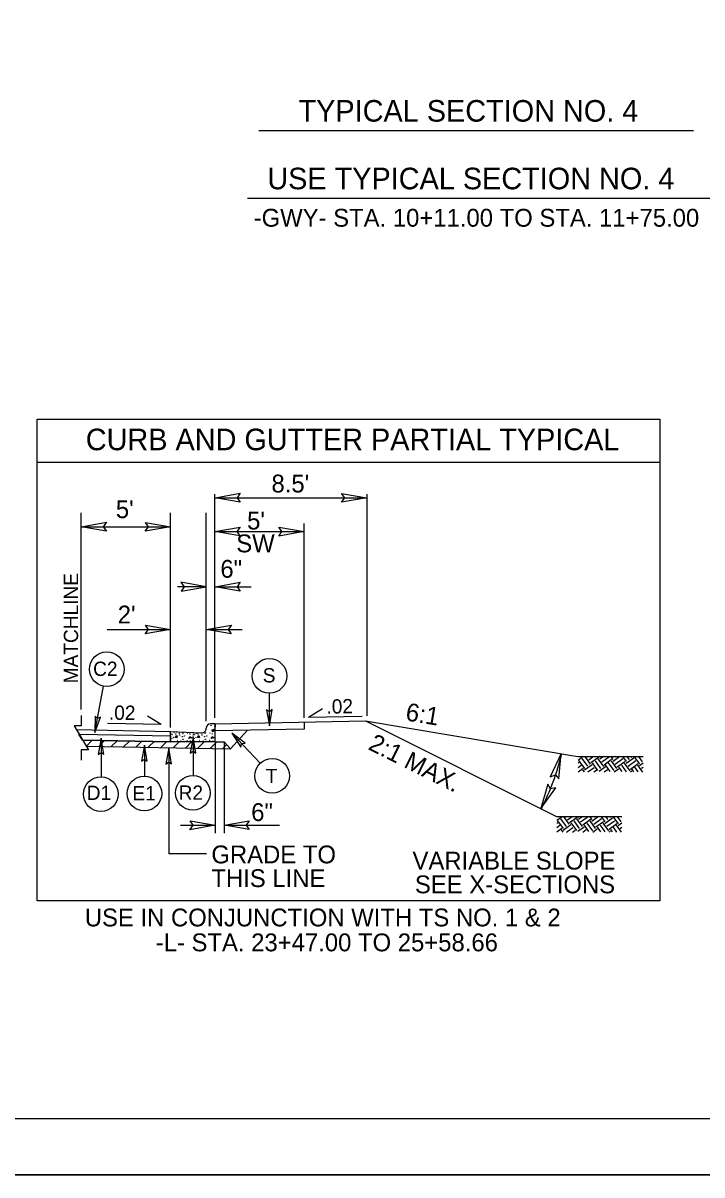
# Model space of a CAD drawing. Extents: x 1184121 to 1184397, y 1246506 to 1246661.
# Drawn here: x 1184280.8 to 1184318.8, y 1246505.7 to 1246570.3 of the extents above; entities that cross this region are included whole.
import ezdxf

# ---------------------------------------------------------------- set-up
doc = ezdxf.new("R2010")
doc.units = 0
for name, color, linetype in [('Prop Shade Light', 7, 'Continuous'), ('Sheet Data Field CELL', 7, 'Continuous'), ('Sheet Plan CELL', 7, 'Continuous'), ('Sheet Plot Border Outside CELL', 7, 'Continuous'), ('Typical Text Label CELL', 7, 'Continuous'), ('z - Construction', 7, 'Continuous')]:
    doc.layers.add(name, color=color, linetype=linetype)

msp = doc.modelspace()

# ---------------------------------------------------------------- linework, layer by layer
at = {"layer": 'Prop Shade Light'}
msp.add_lwpolyline([(1184289.029, 1246529.977), (1184284.1, 1246530.076), (1184283.897, 1246530.413), (1184289.024, 1246530.31), (1184289.029, 1246530.31)], close=True, dxfattribs=at)
at = {"layer": 'Sheet Data Field CELL'}
for p, q in [((1184293.971, 1246564.23), (1184318.347, 1246564.23)), ((1184293.343, 1246560.441), (1184319.777, 1246560.441)), ((1184291.513, 1246531.313), (1184291.513, 1246543.855)), ((1184300.046, 1246531.428), (1184300.046, 1246543.855)), ((1184291.529, 1246543.654), (1184300.046, 1246543.654)), ((1184284.029, 1246531.779), (1184284.029, 1246542.815)), ((1184289.029, 1246530.772), (1184289.029, 1246542.815)), ((1184291.029, 1246531.132), (1184291.029, 1246542.815)), ((1184284.029, 1246542.032), (1184289.029, 1246542.032)), ((1184296.513, 1246532.378), (1184296.513, 1246542.211)), ((1184291.513, 1246541.756), (1184296.513, 1246541.756)), ((1184291.029, 1246538.665), (1184289.425, 1246538.665)), ((1184291.529, 1246538.665), (1184293.551, 1246538.665)), ((1184285.477, 1246536.272), (1184289.029, 1246536.272)), ((1184291.029, 1246536.272), (1184293.051, 1246536.272)), ((1184284.785, 1246530.497), (1184285.281, 1246533.089)), ((1184294.572, 1246530.865), (1184294.571, 1246532.694)), ((1184296.513, 1246531.313), (1184296.513, 1246532.378)), ((1184296.757, 1246531.363), (1184297.54, 1246531.836)), ((1184288.515, 1246530.941), (1184285.499, 1246531.002)), ((1184288.515, 1246530.941), (1184287.732, 1246531.415)), ((1184291.529, 1246530.977), (1184291.268, 1246530.977)), ((1184291.529, 1246530.977), (1184291.523, 1246530.588)), ((1184291.529, 1246530.977), (1184299.967, 1246531.146)), ((1184291.529, 1246529.977), (1184291.529, 1246530.977)), ((1184296.528, 1246531.077), (1184296.522, 1246530.688)), ((1184296.757, 1246531.363), (1184299.774, 1246531.423)), ((1184299.967, 1246531.146), (1184311.858, 1246529.164)), ((1184299.967, 1246531.146), (1184310.665, 1246525.797)), ((1184283.745, 1246530.666), (1184289.029, 1246530.56)), ((1184283.897, 1246530.413), (1184289.024, 1246530.31)), ((1184285.14, 1246530.187), (1184285.14, 1246528.02)), ((1184289.029, 1246530.56), (1184289.029, 1246530.55)), ((1184289.029, 1246529.977), (1184289.029, 1246530.56)), ((1184289.029, 1246530.56), (1184290.779, 1246530.488)), ((1184289.289, 1246530.217), (1184289.376, 1246530.337)), ((1184289.41, 1246530.223), (1184289.289, 1246530.217)), ((1184289.376, 1246530.337), (1184289.41, 1246530.223)), ((1184290.055, 1246530.166), (1184290.117, 1246530.28)), ((1184290.221, 1246530.205), (1184290.055, 1246530.166)), ((1184290.117, 1246530.28), (1184290.221, 1246530.205)), ((1184290.295, 1246530.254), (1184290.295, 1246528.087)), ((1184290.539, 1246530.217), (1184290.625, 1246530.337)), ((1184290.659, 1246530.223), (1184290.539, 1246530.217)), ((1184290.625, 1246530.337), (1184290.659, 1246530.223)), ((1184291.029, 1246530.727), (1184291.029, 1246530.738)), ((1184291.304, 1246530.166), (1184291.366, 1246530.28)), ((1184291.469, 1246530.205), (1184291.304, 1246530.166)), ((1184291.338, 1246530.644), (1184291.355, 1246530.553)), ((1184291.492, 1246530.599), (1184291.338, 1246530.644)), ((1184291.355, 1246530.553), (1184291.492, 1246530.599)), ((1184291.366, 1246530.28), (1184291.469, 1246530.205)), ((1184296.522, 1246530.688), (1184291.523, 1246530.588)), ((1184293.349, 1246530.624), (1184292.394, 1246529.577)), ((1184292.465, 1246530.455), (1184294.061, 1246528.774)), ((1184284.1, 1246530.076), (1184289.029, 1246529.977)), ((1184284.302, 1246529.739), (1184292.394, 1246529.577)), ((1184284.318, 1246529.738), (1184284.645, 1246530.065)), ((1184285.012, 1246529.724), (1184285.338, 1246530.051)), ((1184285.705, 1246529.711), (1184286.031, 1246530.037)), ((1184286.398, 1246529.697), (1184286.725, 1246530.023)), ((1184287.091, 1246529.683), (1184287.418, 1246530.009)), ((1184287.565, 1246529.798), (1184287.565, 1246528.053)), ((1184287.785, 1246529.669), (1184288.111, 1246529.996)), ((1184288.478, 1246529.655), (1184288.805, 1246529.982)), ((1184288.933, 1246529.646), (1184288.933, 1246523.696)), ((1184291.529, 1246529.977), (1184289.029, 1246529.977)), ((1184289.171, 1246529.641), (1184289.507, 1246529.977)), ((1184289.864, 1246529.627), (1184290.214, 1246529.977)), ((1184290.558, 1246529.613), (1184290.922, 1246529.977)), ((1184291.251, 1246529.6), (1184291.629, 1246529.977)), ((1184291.529, 1246529.977), (1184292.029, 1246529.977)), ((1184291.529, 1246529.977), (1184291.529, 1246524.865)), ((1184291.944, 1246529.586), (1184292.175, 1246529.817)), ((1184292.029, 1246529.977), (1184292.394, 1246529.577)), ((1184292.029, 1246529.977), (1184292.029, 1246524.865)), ((1184311.858, 1246529.164), (1184315.513, 1246529.164)), ((1184311.858, 1246529.164), (1184315.513, 1246529.164)), ((1184311.872, 1246528.952), (1184312.168, 1246529.165)), ((1184311.872, 1246528.952), (1184312.168, 1246529.165)), ((1184312.251, 1246528.491), (1184311.942, 1246528.921)), ((1184312.251, 1246528.491), (1184311.942, 1246528.921)), ((1184312.412, 1246528.607), (1184312.103, 1246529.037)), ((1184312.412, 1246528.607), (1184312.103, 1246529.037)), ((1184312.573, 1246528.723), (1184312.264, 1246529.152)), ((1184312.573, 1246528.723), (1184312.264, 1246529.152)), ((1184312.357, 1246529.137), (1184312.395, 1246529.165)), ((1184312.357, 1246529.137), (1184312.395, 1246529.165)), ((1184312.473, 1246528.976), (1184312.737, 1246529.166)), ((1184312.473, 1246528.976), (1184312.737, 1246529.166)), ((1184312.588, 1246528.815), (1184313.018, 1246529.124)), ((1184312.588, 1246528.815), (1184313.018, 1246529.124)), ((1184313.15, 1246528.486), (1184312.842, 1246528.916)), ((1184313.15, 1246528.486), (1184312.842, 1246528.916)), ((1184313.312, 1246528.602), (1184313.003, 1246529.032)), ((1184313.312, 1246528.602), (1184313.003, 1246529.032)), ((1184313.11, 1246529.109), (1184313.068, 1246529.167)), ((1184313.11, 1246529.109), (1184313.068, 1246529.167)), ((1184313.095, 1246529.016), (1184313.306, 1246529.168)), ((1184313.095, 1246529.016), (1184313.306, 1246529.168)), ((1184313.211, 1246528.855), (1184313.641, 1246529.164)), ((1184313.211, 1246528.855), (1184313.641, 1246529.164)), ((1184313.327, 1246528.694), (1184313.756, 1246529.003)), ((1184313.327, 1246528.694), (1184313.756, 1246529.003)), ((1184313.849, 1246528.988), (1184313.719, 1246529.169)), ((1184313.849, 1246528.988), (1184313.719, 1246529.169)), ((1184314.05, 1246528.481), (1184313.741, 1246528.911)), ((1184314.05, 1246528.481), (1184313.741, 1246528.911)), ((1184313.834, 1246528.896), (1184314.216, 1246529.17)), ((1184313.834, 1246528.896), (1184314.216, 1246529.17)), ((1184313.949, 1246528.734), (1184314.379, 1246529.043)), ((1184313.949, 1246528.734), (1184314.379, 1246529.043)), ((1184314.01, 1246529.104), (1184313.962, 1246529.17)), ((1184314.01, 1246529.104), (1184313.962, 1246529.17)), ((1184314.065, 1246528.573), (1184314.495, 1246528.882)), ((1184314.065, 1246528.573), (1184314.495, 1246528.882)), ((1184314.587, 1246528.867), (1184314.374, 1246529.164)), ((1184314.587, 1246528.867), (1184314.374, 1246529.164)), ((1184314.572, 1246528.775), (1184315.002, 1246529.083)), ((1184314.572, 1246528.775), (1184315.002, 1246529.083)), ((1184314.748, 1246528.983), (1184314.613, 1246529.172)), ((1184314.748, 1246528.983), (1184314.613, 1246529.172)), ((1184314.688, 1246528.614), (1184315.117, 1246528.922)), ((1184314.688, 1246528.614), (1184315.117, 1246528.922)), ((1184314.909, 1246529.099), (1184314.862, 1246529.164)), ((1184314.909, 1246529.099), (1184314.862, 1246529.164)), ((1184315.326, 1246528.746), (1184315.025, 1246529.164)), ((1184315.326, 1246528.746), (1184315.025, 1246529.164)), ((1184315.487, 1246528.862), (1184315.27, 1246529.164)), ((1184315.487, 1246528.862), (1184315.27, 1246529.164)), ((1184311.872, 1246528.789), (1184311.927, 1246528.829)), ((1184311.872, 1246528.789), (1184311.927, 1246528.829)), ((1184311.872, 1246528.545), (1184312.043, 1246528.667)), ((1184311.872, 1246528.545), (1184312.043, 1246528.667)), ((1184311.872, 1246528.301), (1184312.159, 1246528.506)), ((1184311.872, 1246528.301), (1184312.159, 1246528.506)), ((1184312.233, 1246528.29), (1184312.144, 1246528.414)), ((1184312.233, 1246528.29), (1184312.144, 1246528.414)), ((1184312.236, 1246528.399), (1184312.665, 1246528.708)), ((1184312.236, 1246528.399), (1184312.665, 1246528.708)), ((1184312.424, 1246528.29), (1184312.781, 1246528.547)), ((1184312.424, 1246528.29), (1184312.781, 1246528.547)), ((1184312.989, 1246528.37), (1184312.681, 1246528.8)), ((1184312.989, 1246528.37), (1184312.681, 1246528.8)), ((1184312.764, 1246528.29), (1184312.897, 1246528.385)), ((1184312.764, 1246528.29), (1184312.897, 1246528.385)), ((1184313.051, 1246528.333), (1184313.404, 1246528.587)), ((1184313.051, 1246528.333), (1184313.404, 1246528.587)), ((1184313.33, 1246528.29), (1184313.52, 1246528.426)), ((1184313.33, 1246528.29), (1184313.52, 1246528.426)), ((1184313.677, 1246528.321), (1184313.419, 1246528.679)), ((1184313.677, 1246528.321), (1184313.419, 1246528.679)), ((1184313.889, 1246528.365), (1184313.58, 1246528.795)), ((1184313.889, 1246528.365), (1184313.58, 1246528.795)), ((1184313.897, 1246528.29), (1184314.142, 1246528.466)), ((1184313.897, 1246528.29), (1184314.142, 1246528.466)), ((1184314.338, 1246528.307), (1184314.157, 1246528.558)), ((1184314.338, 1246528.307), (1184314.157, 1246528.558)), ((1184314.586, 1246528.302), (1184314.319, 1246528.674)), ((1184314.586, 1246528.302), (1184314.319, 1246528.674)), ((1184314.788, 1246528.36), (1184314.48, 1246528.79)), ((1184314.788, 1246528.36), (1184314.48, 1246528.79)), ((1184314.804, 1246528.452), (1184315.233, 1246528.761)), ((1184314.804, 1246528.452), (1184315.233, 1246528.761)), ((1184314.815, 1246528.298), (1184314.881, 1246528.345)), ((1184314.815, 1246528.298), (1184314.881, 1246528.345)), ((1184314.999, 1246528.294), (1184314.896, 1246528.437)), ((1184314.999, 1246528.294), (1184314.896, 1246528.437)), ((1184315.247, 1246528.289), (1184315.057, 1246528.553)), ((1184315.247, 1246528.289), (1184315.057, 1246528.553)), ((1184315.495, 1246528.284), (1184315.218, 1246528.669)), ((1184315.495, 1246528.284), (1184315.218, 1246528.669)), ((1184315.31, 1246528.654), (1184315.513, 1246528.799)), ((1184315.31, 1246528.654), (1184315.513, 1246528.799)), ((1184315.426, 1246528.493), (1184315.513, 1246528.555)), ((1184315.426, 1246528.493), (1184315.513, 1246528.555)), ((1184310.665, 1246525.797), (1184314.319, 1246525.797)), ((1184310.665, 1246525.797), (1184314.319, 1246525.797)), ((1184310.679, 1246525.585), (1184310.974, 1246525.798)), ((1184310.679, 1246525.585), (1184310.974, 1246525.798)), ((1184311.218, 1246525.24), (1184310.909, 1246525.67)), ((1184311.218, 1246525.24), (1184310.909, 1246525.67)), ((1184311.379, 1246525.356), (1184311.071, 1246525.786)), ((1184311.379, 1246525.356), (1184311.071, 1246525.786)), ((1184311.163, 1246525.771), (1184311.202, 1246525.798)), ((1184311.163, 1246525.771), (1184311.202, 1246525.798)), ((1184311.279, 1246525.609), (1184311.543, 1246525.799)), ((1184311.279, 1246525.609), (1184311.543, 1246525.799)), ((1184311.394, 1246525.448), (1184311.824, 1246525.757)), ((1184311.394, 1246525.448), (1184311.824, 1246525.757)), ((1184312.118, 1246525.235), (1184311.809, 1246525.665)), ((1184312.118, 1246525.235), (1184311.809, 1246525.665)), ((1184311.916, 1246525.742), (1184311.874, 1246525.8)), ((1184311.916, 1246525.742), (1184311.874, 1246525.8)), ((1184311.901, 1246525.65), (1184312.112, 1246525.801)), ((1184311.901, 1246525.65), (1184312.112, 1246525.801)), ((1184312.017, 1246525.489), (1184312.447, 1246525.797)), ((1184312.017, 1246525.489), (1184312.447, 1246525.797)), ((1184312.133, 1246525.327), (1184312.562, 1246525.636)), ((1184312.133, 1246525.327), (1184312.562, 1246525.636)), ((1184312.655, 1246525.621), (1184312.525, 1246525.802)), ((1184312.655, 1246525.621), (1184312.525, 1246525.802)), ((1184312.64, 1246525.529), (1184313.022, 1246525.804)), ((1184312.64, 1246525.529), (1184313.022, 1246525.804)), ((1184312.755, 1246525.368), (1184313.185, 1246525.676)), ((1184312.755, 1246525.368), (1184313.185, 1246525.676)), ((1184312.816, 1246525.737), (1184312.768, 1246525.803)), ((1184312.816, 1246525.737), (1184312.768, 1246525.803)), ((1184313.393, 1246525.5), (1184313.18, 1246525.797)), ((1184313.393, 1246525.5), (1184313.18, 1246525.797)), ((1184313.378, 1246525.408), (1184313.808, 1246525.717)), ((1184313.378, 1246525.408), (1184313.808, 1246525.717)), ((1184313.554, 1246525.616), (1184313.419, 1246525.805)), ((1184313.554, 1246525.616), (1184313.419, 1246525.805)), ((1184313.715, 1246525.732), (1184313.668, 1246525.797)), ((1184313.715, 1246525.732), (1184313.668, 1246525.797)), ((1184314.132, 1246525.379), (1184313.831, 1246525.797)), ((1184314.132, 1246525.379), (1184313.831, 1246525.797)), ((1184314.293, 1246525.495), (1184314.076, 1246525.797)), ((1184314.293, 1246525.495), (1184314.076, 1246525.797)), ((1184289.594, 1246525.301), (1184291.529, 1246525.301)), ((1184292.029, 1246525.301), (1184295.133, 1246525.301)), ((1184310.679, 1246525.423), (1184310.733, 1246525.462)), ((1184310.679, 1246525.423), (1184310.733, 1246525.462)), ((1184310.679, 1246525.178), (1184310.849, 1246525.301)), ((1184310.679, 1246525.178), (1184310.849, 1246525.301)), ((1184310.679, 1246524.934), (1184310.965, 1246525.14)), ((1184310.679, 1246524.934), (1184310.965, 1246525.14)), ((1184311.057, 1246525.124), (1184310.748, 1246525.554)), ((1184311.057, 1246525.124), (1184310.748, 1246525.554)), ((1184311.039, 1246524.923), (1184310.95, 1246525.047)), ((1184311.039, 1246524.923), (1184310.95, 1246525.047)), ((1184311.042, 1246525.032), (1184311.472, 1246525.341)), ((1184311.042, 1246525.032), (1184311.472, 1246525.341)), ((1184311.23, 1246524.923), (1184311.587, 1246525.18)), ((1184311.23, 1246524.923), (1184311.587, 1246525.18)), ((1184311.795, 1246525.004), (1184311.487, 1246525.433)), ((1184311.795, 1246525.004), (1184311.487, 1246525.433)), ((1184311.57, 1246524.923), (1184311.703, 1246525.019)), ((1184311.57, 1246524.923), (1184311.703, 1246525.019)), ((1184311.957, 1246525.119), (1184311.648, 1246525.549)), ((1184311.957, 1246525.119), (1184311.648, 1246525.549)), ((1184311.857, 1246524.966), (1184312.21, 1246525.22)), ((1184311.857, 1246524.966), (1184312.21, 1246525.22)), ((1184312.136, 1246524.923), (1184312.326, 1246525.059)), ((1184312.136, 1246524.923), (1184312.326, 1246525.059)), ((1184312.483, 1246524.954), (1184312.225, 1246525.312)), ((1184312.483, 1246524.954), (1184312.225, 1246525.312)), ((1184312.695, 1246524.998), (1184312.386, 1246525.428)), ((1184312.695, 1246524.998), (1184312.386, 1246525.428)), ((1184312.856, 1246525.114), (1184312.547, 1246525.544)), ((1184312.856, 1246525.114), (1184312.547, 1246525.544)), ((1184312.703, 1246524.923), (1184312.948, 1246525.099)), ((1184312.703, 1246524.923), (1184312.948, 1246525.099)), ((1184312.871, 1246525.207), (1184313.301, 1246525.515)), ((1184312.871, 1246525.207), (1184313.301, 1246525.515)), ((1184313.144, 1246524.941), (1184312.964, 1246525.191)), ((1184313.144, 1246524.941), (1184312.964, 1246525.191)), ((1184313.392, 1246524.936), (1184313.125, 1246525.307)), ((1184313.392, 1246524.936), (1184313.125, 1246525.307)), ((1184313.595, 1246524.993), (1184313.286, 1246525.423)), ((1184313.595, 1246524.993), (1184313.286, 1246525.423)), ((1184313.494, 1246525.247), (1184313.924, 1246525.556)), ((1184313.494, 1246525.247), (1184313.924, 1246525.556)), ((1184313.61, 1246525.086), (1184314.039, 1246525.394)), ((1184313.61, 1246525.086), (1184314.039, 1246525.394)), ((1184313.805, 1246524.927), (1184313.702, 1246525.071)), ((1184313.805, 1246524.927), (1184313.702, 1246525.071)), ((1184314.053, 1246524.922), (1184313.863, 1246525.186)), ((1184314.053, 1246524.922), (1184313.863, 1246525.186)), ((1184314.301, 1246524.917), (1184314.024, 1246525.302)), ((1184314.301, 1246524.917), (1184314.024, 1246525.302)), ((1184314.117, 1246525.287), (1184314.319, 1246525.432)), ((1184314.117, 1246525.287), (1184314.319, 1246525.432)), ((1184314.232, 1246525.126), (1184314.319, 1246525.188)), ((1184314.232, 1246525.126), (1184314.319, 1246525.188)), ((1184313.621, 1246524.931), (1184313.687, 1246524.978)), ((1184313.621, 1246524.931), (1184313.687, 1246524.978)), ((1184291.051, 1246523.696), (1184288.933, 1246523.696))]:
    msp.add_line(p, q, dxfattribs=at)
for points in [[(1184292.935, 1246543.412), (1184291.529, 1246543.654), (1184292.943, 1246543.904), (1184292.763, 1246543.654)], [(1184298.621, 1246543.896), (1184300.027, 1246543.654), (1184298.613, 1246543.404), (1184298.792, 1246543.654)], [(1184285.435, 1246541.79), (1184284.029, 1246542.032), (1184285.443, 1246542.282), (1184285.263, 1246542.032)], [(1184287.623, 1246542.274), (1184289.029, 1246542.032), (1184287.615, 1246541.782), (1184287.795, 1246542.032)], [(1184292.919, 1246541.514), (1184291.513, 1246541.756), (1184292.926, 1246542.006), (1184292.747, 1246541.756)], [(1184295.107, 1246541.998), (1184296.513, 1246541.756), (1184295.099, 1246541.506), (1184295.278, 1246541.756)], [(1184289.623, 1246538.423), (1184291.029, 1246538.665), (1184289.615, 1246538.915), (1184289.795, 1246538.665)], [(1184292.935, 1246538.423), (1184291.529, 1246538.665), (1184292.943, 1246538.915), (1184292.763, 1246538.665)], [(1184287.623, 1246536.514), (1184289.029, 1246536.272), (1184287.615, 1246536.022), (1184287.795, 1246536.272)], [(1184292.435, 1246536.03), (1184291.029, 1246536.272), (1184292.443, 1246536.522), (1184292.263, 1246536.272)], [(1184294.415, 1246531.774), (1184294.572, 1246530.865), (1184294.734, 1246531.78), (1184294.572, 1246531.663)], [(1184284.798, 1246531.42), (1184284.785, 1246530.497), (1184285.112, 1246531.366), (1184284.931, 1246531.282)], [(1184285.297, 1246529.277), (1184285.14, 1246530.187), (1184284.979, 1246529.272), (1184285.14, 1246529.388)], [(1184290.451, 1246529.344), (1184290.295, 1246530.254), (1184290.133, 1246529.339), (1184290.295, 1246529.455)], [(1184293.205, 1246529.903), (1184292.465, 1246530.455), (1184292.978, 1246529.68), (1184293.015, 1246529.876)], [(1184287.721, 1246528.889), (1184287.565, 1246529.798), (1184287.403, 1246528.884), (1184287.565, 1246529)], [(1184289.09, 1246528.736), (1184288.933, 1246529.646), (1184288.772, 1246528.731), (1184288.933, 1246528.847)], [(1184310.79, 1246527.899), (1184310.926, 1246529.319), (1184310.314, 1246528.021), (1184310.602, 1246528.128)], [(1184310.186, 1246527.607), (1184309.783, 1246526.238), (1184310.631, 1246527.396), (1184310.327, 1246527.346)], [(1184290.123, 1246525.543), (1184291.529, 1246525.301), (1184290.115, 1246525.051), (1184290.295, 1246525.301)], [(1184293.435, 1246525.059), (1184292.029, 1246525.301), (1184293.443, 1246525.551), (1184293.263, 1246525.301)]]:
    msp.add_lwpolyline(points, close=True, dxfattribs=at)
msp.add_lwpolyline([(1184284.029, 1246531.46), (1184284.029, 1246530.871), (1184283.622, 1246530.871), (1184284.429, 1246529.527), (1184284.021, 1246529.527), (1184284.021, 1246528.953)], dxfattribs=at)
for centre, radius in [((1184285.458, 1246534.045), 0.972), ((1184294.572, 1246533.667), 0.972), ((1184291.298, 1246530.901), 0.00802), ((1184291.515, 1246530.867), 0.00802), ((1184289.046, 1246530.314), 0.00802), ((1184289.063, 1246530.411), 0.00802), ((1184289.103, 1246530.171), 0.00802), ((1184289.119, 1246530.377), 0.00802), ((1184289.199, 1246530.217), 0.00802), ((1184289.227, 1246530.502), 0.00802), ((1184289.324, 1246530.417), 0.00802), ((1184289.37, 1246530.519), 0.00802), ((1184289.518, 1246530.456), 0.00802), ((1184289.547, 1246530.354), 0.00802), ((1184289.695, 1246530.269), 0.00802), ((1184289.724, 1246530.44), 0.00802), ((1184289.741, 1246530.49), 0.00802), ((1184289.821, 1246530.297), 0.00802), ((1184289.998, 1246530.462), 0.00802), ((1184290.118, 1246530.411), 0.00802), ((1184290.295, 1246530.314), 0.00802), ((1184290.312, 1246530.411), 0.00802), ((1184290.352, 1246530.171), 0.00802), ((1184290.368, 1246530.377), 0.00802), ((1184290.448, 1246530.217), 0.00802), ((1184290.476, 1246530.46), 0.00802), ((1184290.573, 1246530.417), 0.00802), ((1184290.767, 1246530.456), 0.00802), ((1184290.796, 1246530.354), 0.00802), ((1184290.944, 1246530.269), 0.00802), ((1184290.973, 1246530.44), 0.00802), ((1184290.99, 1246530.49), 0.00802), ((1184291.07, 1246530.297), 0.00802), ((1184291.247, 1246530.462), 0.00802), ((1184291.367, 1246530.411), 0.00802), ((1184291.464, 1246530.684), 0.00802), ((1184289.04, 1246530.006), 0.00802), ((1184289.25, 1246529.983), 0.00802), ((1184289.41, 1246530.052), 0.00802), ((1184289.615, 1246530.029), 0.00802), ((1184289.729, 1246530.114), 0.00802), ((1184289.787, 1246530), 0.00802), ((1184289.964, 1246530.063), 0.00802), ((1184290.135, 1246530.023), 0.00802), ((1184290.289, 1246530.006), 0.00802), ((1184290.499, 1246529.983), 0.00802), ((1184290.659, 1246530.052), 0.00802), ((1184290.864, 1246530.029), 0.00802), ((1184290.979, 1246530.114), 0.00802), ((1184291.036, 1246530), 0.00802), ((1184291.213, 1246530.063), 0.00802), ((1184291.384, 1246530.023), 0.00802), ((1184294.731, 1246528.069), 0.972), ((1184285.126, 1246527.048), 0.972), ((1184287.563, 1246527.081), 0.972), ((1184290.281, 1246527.115), 0.972)]:
    msp.add_circle(centre, radius, dxfattribs=at)
for centre, radius, start, end in [((1184291.268, 1246530.738), 0.24, 90, 180), ((1184290.789, 1246530.727), 0.24, 267.61554, 0), ((1184296.375, 1246532.964), 15.037, 333.35912, 345.93754)]:
    msp.add_arc(centre, radius, start, end, dxfattribs=at)
at = {"layer": 'Sheet Plan CELL'}
msp.add_line((1184126.181, 1246508.875), (1184358.419, 1246508.875), dxfattribs=at)
at = {"layer": 'Sheet Plot Border Outside CELL'}
msp.add_lwpolyline([(1184121.05, 1246660.53), (1184360.324, 1246660.53), (1184360.324, 1246505.708), (1184121.05, 1246505.708)], close=True, dxfattribs=at)
at = {"layer": 'Typical Text Label CELL'}
msp.add_line((1184281.556, 1246545.648), (1184316.449, 1246545.648), dxfattribs=at)
msp.add_lwpolyline([(1184281.556, 1246548.062), (1184316.449, 1246548.062), (1184316.449, 1246521.07), (1184281.556, 1246521.07)], close=True, dxfattribs=at)
at = {"layer": 'z - Construction'}
msp.add_line((1184121.05, 1246505.708), (1184360.324, 1246505.708), dxfattribs=at)

# ---------------------------------------------------------------- texts
at = {"layer": 'Sheet Data Field CELL'}
for s, height, p in [('TYPICAL SECTION NO. 4', 1.20892, (1184296.207, 1246564.727)), ('USE TYPICAL SECTION NO. 4', 1.20892, (1184294.455, 1246560.937)), ('CURB AND GUTTER PARTIAL TYPICAL', 1.20892, (1184284.28, 1246546.316)), ('C2', 0.8, (1184284.691, 1246533.669)), ('D1', 0.8, (1184284.333, 1246526.722)), ('E1', 0.8, (1184286.891, 1246526.695)), ('R2', 0.8, (1184289.484, 1246526.731)), ('GRADE TO ', 1, (1184291.32, 1246523.167)), ('THIS LINE', 1, (1184291.32, 1246521.838))]:
    msp.add_text(s, height=height, dxfattribs=at).set_placement(p)
for s, height, rotation, p in [('-GWY- STA. 10+11.00 TO STA. 11+75.00', 1, 0.00023, (1184293.691, 1246558.841)), ("8.5'", 1, 359.99948, (1184294.689, 1246543.948)), ("5'", 1, 359.99977, (1184285.966, 1246542.514)), ("5'", 1, 359.99948, (1184293.323, 1246541.874)), ('SW', 1, 359.99948, (1184292.716, 1246540.594)), ('6"', 1, 359.99948, (1184291.823, 1246539.171)), ('MATCHLINE', 0.8, 90, (1184283.849, 1246533.255)), ("2'", 1, 359.99977, (1184286.072, 1246536.61)), ('S', 0.8, 0.00029, (1184294.199, 1246533.304)), ('.02', 0.8, 1.14596, (1184297.777, 1246531.551)), ('6:1', 1, 350.53748, (1184302.161, 1246531.186)), ('.02', 0.8, 359.45976, (1184285.574, 1246531.217)), ('2:1 MAX.', 1, 333.43475, (1184300.055, 1246529.58)), ('T', 0.8, 359.99971, (1184294.362, 1246527.661)), ('6"', 1, 359.99977, (1184293.552, 1246525.538)), ('VARIABLE SLOPE', 1, 360, (1184302.594, 1246522.819)), ('SEE X-SECTIONS', 1, 360, (1184302.727, 1246521.49)), ('USE IN CONJUNCTION WITH TS NO. 1 & 2', 1, 0.00023, (1184284.225, 1246519.634)), ('-L- STA. 23+47.00 TO 25+58.66', 1, 0.00023, (1184288.202, 1246518.239))]:
    msp.add_text(s, height=height, rotation=rotation, dxfattribs=at).set_placement(p)

doc.saveas('drawing.dxf')
